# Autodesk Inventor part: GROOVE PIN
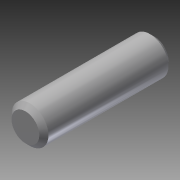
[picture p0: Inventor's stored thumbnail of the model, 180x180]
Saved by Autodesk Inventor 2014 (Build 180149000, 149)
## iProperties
Shininess: 64.0
Length Units: 11272
Angle Units: 11279
Time Units: 11290
Mass Units: 11286
Length Display Precision: 3
Angle Display Precision: 2
Compacted: True
Part Number: GROOVE PIN
Document SubType Name: Modeling
Created: 2003-11
Designer: Autodesk, Inc.
Manufacturer: Standard
Standards Organization: Custom
Mass: 5.44307 g
Surface Area: 4.86691 cm^2
Volume: 0.692502 cm^3
Density: 7.86 g/cm^3
Material: Steel, Mild
Appearance: Steel
Density: 0.0
Volumn: 0.0
Area: 0.0
PropertySet Name: Model Information
Control State: 0
Master: False
Checked Out: False
Author: Autodesk, Inc.
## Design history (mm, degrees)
sketch "Sketch1"
  geometry: C1 r 3.175 at (0, 0); 1 further point
  constraints: 1 centre point, 1 coincident
  dimensions: "d0" = 6.35 diameter of C1
extrude "Extrusion1" new body sketch "Sketch1" distance "d1" = 22.225; taper "d2" = 0 deg
chamfer "Chamfer1" distance "d3" = 0.7874; stored, may be unused: second distance "d4" = 3.175, angle "d5" = 45 deg
body "Solid1"
